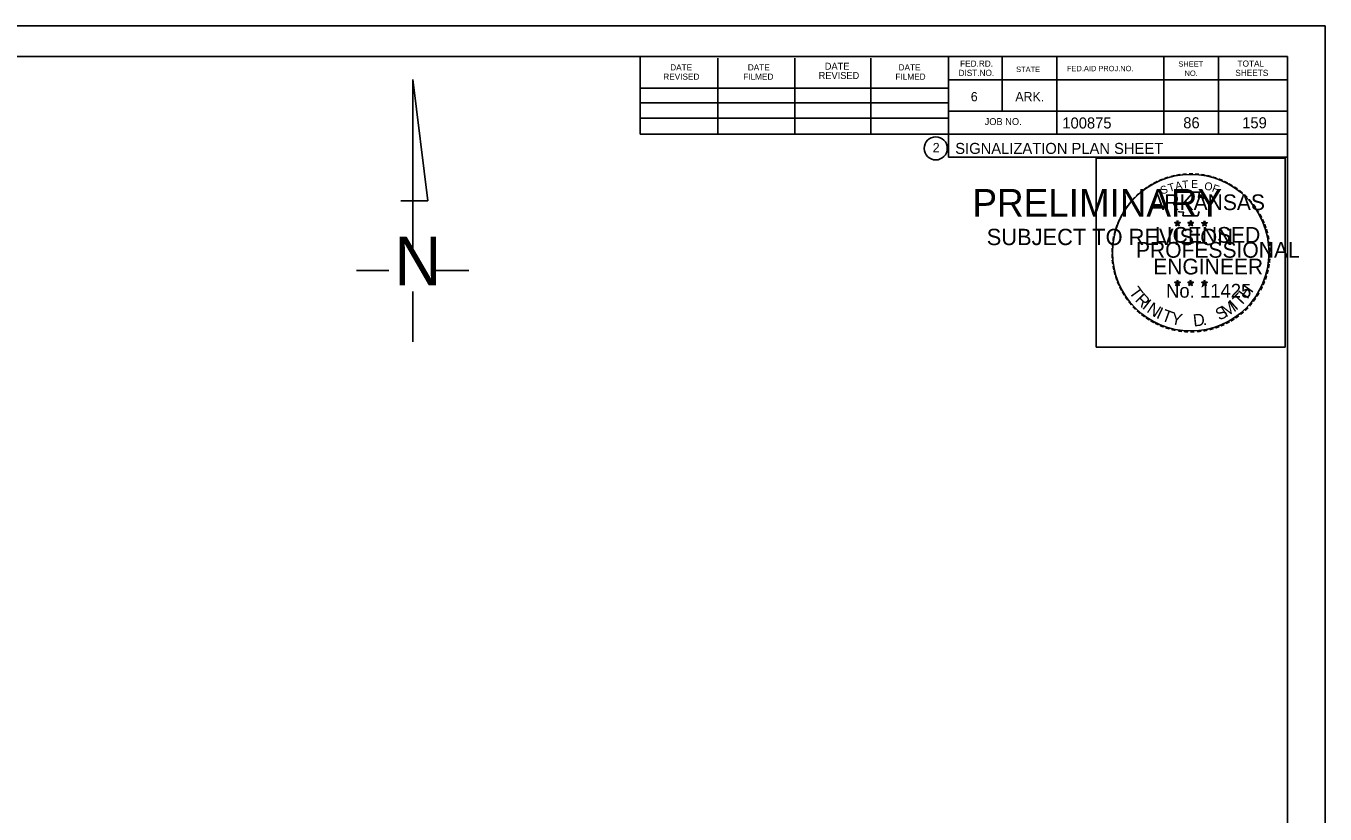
# Model space of a CAD drawing. Extents: x 1712074 to 1713074, y 558397 to 559037.
# Drawn here: x 1712578.9 to 1713074.1, y 558736.4 to 559037 of the extents above; entities that cross this region are included whole.
import ezdxf

# ---------------------------------------------------------------- set-up
doc = ezdxf.new("R2010")
doc.units = 0
for name, color, linetype in [('R_Border', 7, 'Continuous'), ('R_Border PE', 7, 'Continuous'), ('R_Border Prem', 7, 'Continuous'), ('R_Draft', 7, 'Continuous'), ('R_No Plot', 7, 'Continuous')]:
    doc.layers.add(name, color=color, linetype=linetype)

msp = doc.modelspace()

# ---------------------------------------------------------------- linework, layer by layer
at = {"layer": 'R_Border'}
for p, q in [((1712111.35, 559025.27), (1713059.89, 559025.27)), ((1712813.11, 558995.63), (1712813.11, 559025.27)), ((1712842.69, 558995.63), (1712842.69, 559024.67)), ((1712871.97, 558995.63), (1712871.97, 559024.67)), ((1712901.01, 558995.63), (1712901.01, 559024.67)), ((1712930.59, 559025.27), (1712930.59, 558986.87)), ((1712951.11, 559025.27), (1712951.11, 559004.45)), ((1712971.93, 559025.27), (1712971.93, 558995.63)), ((1713012.67, 559025.27), (1713012.67, 558995.63)), ((1713033.49, 559025.27), (1713033.49, 558995.63)), ((1713059.89, 558408.89), (1713059.89, 559025.27)), ((1713059.89, 559016.45), (1712930.59, 559016.45)), ((1713059.89, 559016.51), (1713059.89, 559016.51)), ((1712813.11, 559013.21), (1712930.59, 559013.21)), ((1712813.11, 559007.63), (1712930.59, 559007.63)), ((1713059.89, 559004.45), (1712930.59, 559004.45)), ((1712939.47, 559004.45), (1713059.89, 559004.45)), ((1712813.11, 558995.63), (1712813.11, 559001.81)), ((1712813.11, 559001.81), (1712930.59, 559001.81)), ((1713059.89, 558995.63), (1712813.11, 558995.63)), ((1712930.59, 558986.87), (1713059.89, 558986.87))]:
    msp.add_line(p, q, dxfattribs=at)
msp.add_circle((1712925.75, 558990.27), 4.4, dxfattribs=at)
at = {"layer": 'R_Border PE'}
for p, q in [((1713016.87, 558961.95), (1713017.92, 558961.62)), ((1713016.87, 558961.95), (1713017.63, 558961.81)), ((1713016.87, 558961.95), (1713017.58, 558961.58)), ((1713017.27, 558960.73), (1713017.92, 558961.62)), ((1713017.27, 558960.73), (1713017.65, 558961.46)), ((1713017.27, 558960.73), (1713017.91, 558961.38)), ((1713017.92, 558962.71), (1713017.79, 558961.96)), ((1713018.55, 558960.73), (1713017.91, 558961.37)), ((1713017.92, 558961.62), (1713017.92, 558962.71)), ((1713017.92, 558962.71), (1713018.06, 558961.96)), ((1713018.96, 558961.95), (1713017.92, 558961.62)), ((1713018.55, 558960.73), (1713017.92, 558961.62)), ((1713018.96, 558961.95), (1713018.1, 558961.8)), ((1713018.55, 558960.73), (1713018.14, 558961.6)), ((1713018.96, 558961.95), (1713018.34, 558961.64)), ((1713021.88, 558961.95), (1713022.93, 558961.62)), ((1713021.88, 558961.95), (1713022.64, 558961.81)), ((1713021.88, 558961.95), (1713022.59, 558961.58)), ((1713022.28, 558960.73), (1713022.93, 558961.62)), ((1713022.28, 558960.73), (1713022.66, 558961.46)), ((1713022.28, 558960.73), (1713022.92, 558961.38)), ((1713022.93, 558962.71), (1713022.8, 558961.96)), ((1713023.56, 558960.73), (1713022.92, 558961.37)), ((1713022.93, 558961.62), (1713022.93, 558962.71)), ((1713022.93, 558962.71), (1713023.07, 558961.96)), ((1713023.97, 558961.95), (1713022.93, 558961.62)), ((1713023.56, 558960.73), (1713022.93, 558961.62)), ((1713023.97, 558961.95), (1713023.11, 558961.8)), ((1713023.56, 558960.73), (1713023.15, 558961.6)), ((1713023.97, 558961.95), (1713023.35, 558961.64)), ((1713027.17, 558961.91), (1713028.22, 558961.58)), ((1713027.17, 558961.91), (1713027.93, 558961.78)), ((1713027.17, 558961.91), (1713027.88, 558961.55)), ((1713027.57, 558960.69), (1713028.22, 558961.58)), ((1713027.57, 558960.69), (1713027.95, 558961.42)), ((1713027.57, 558960.69), (1713028.21, 558961.34)), ((1713028.22, 558962.68), (1713028.09, 558961.92)), ((1713028.86, 558960.69), (1713028.21, 558961.33)), ((1713028.22, 558961.58), (1713028.22, 558962.68)), ((1713028.22, 558962.68), (1713028.36, 558961.93)), ((1713029.26, 558961.91), (1713028.22, 558961.58)), ((1713028.86, 558960.69), (1713028.22, 558961.58)), ((1713029.26, 558961.91), (1713028.4, 558961.77)), ((1713028.86, 558960.69), (1713028.45, 558961.56)), ((1713029.26, 558961.91), (1713028.65, 558961.61)), ((1713017.9, 558939.99), (1713017.78, 558939.24)), ((1713017.9, 558938.9), (1713017.9, 558939.99)), ((1713017.9, 558939.99), (1713018.05, 558939.24)), ((1713022.91, 558939.99), (1713022.79, 558939.24)), ((1713022.91, 558938.9), (1713022.91, 558939.99)), ((1713022.91, 558939.99), (1713023.06, 558939.24)), ((1713028.21, 558939.96), (1713028.09, 558939.21)), ((1713028.21, 558938.87), (1713028.21, 558939.96)), ((1713028.21, 558939.96), (1713028.36, 558939.21)), ((1713016.86, 558939.23), (1713017.9, 558938.9)), ((1713016.86, 558939.23), (1713017.62, 558939.1)), ((1713016.86, 558939.23), (1713017.57, 558938.86)), ((1713017.26, 558938.01), (1713017.9, 558938.9)), ((1713017.26, 558938.01), (1713017.63, 558938.74)), ((1713017.26, 558938.01), (1713017.9, 558938.66)), ((1713018.94, 558939.23), (1713017.9, 558938.9)), ((1713018.54, 558938.01), (1713017.9, 558938.9)), ((1713018.54, 558938.01), (1713017.9, 558938.65)), ((1713018.94, 558939.23), (1713018.09, 558939.08)), ((1713018.54, 558938.01), (1713018.13, 558938.88)), ((1713018.94, 558939.23), (1713018.33, 558938.92)), ((1713021.86, 558939.23), (1713022.91, 558938.9)), ((1713021.86, 558939.23), (1713022.62, 558939.1)), ((1713021.86, 558939.23), (1713022.57, 558938.86)), ((1713022.26, 558938.01), (1713022.91, 558938.9)), ((1713022.26, 558938.01), (1713022.64, 558938.74)), ((1713022.26, 558938.01), (1713022.9, 558938.66)), ((1713023.55, 558938.01), (1713022.9, 558938.65)), ((1713023.95, 558939.23), (1713022.91, 558938.9)), ((1713023.55, 558938.01), (1713022.91, 558938.9)), ((1713023.95, 558939.23), (1713023.09, 558939.08)), ((1713023.55, 558938.01), (1713023.14, 558938.88)), ((1713023.95, 558939.23), (1713023.34, 558938.92)), ((1713027.16, 558939.2), (1713028.21, 558938.87)), ((1713027.16, 558939.2), (1713027.92, 558939.07)), ((1713027.16, 558939.2), (1713027.88, 558938.83)), ((1713027.56, 558937.98), (1713028.21, 558938.87)), ((1713027.56, 558937.98), (1713027.94, 558938.71)), ((1713027.56, 558937.98), (1713028.21, 558938.63)), ((1713029.25, 558939.2), (1713028.21, 558938.87)), ((1713028.85, 558937.98), (1713028.21, 558938.87)), ((1713028.85, 558937.98), (1713028.21, 558938.62)), ((1713029.25, 558939.2), (1713028.39, 558939.05)), ((1713028.85, 558937.98), (1713028.44, 558938.85)), ((1713029.25, 558939.2), (1713028.64, 558938.89))]:
    msp.add_line(p, q, dxfattribs=at)
for points in [[(1713016.99, 558973.58), (1713017.8, 558971.1)], [(1713027.52, 558970.82), (1713027.95, 558971.67), (1713025.9, 558971.6), (1713026.34, 558973.58), (1713016.99, 558973.58)], [(1713018.47, 558966.31), (1713018.47, 558966.05), (1713020.16, 558966), (1713019.99, 558964.58), (1713025.6, 558964.58), (1713026.21, 558966.19)], [(1713017.92, 558962.71), (1713018.55, 558960.73), (1713016.87, 558961.95), (1713018.96, 558961.95), (1713017.27, 558960.73), (1713017.92, 558962.71)], [(1713022.93, 558962.71), (1713023.56, 558960.73), (1713021.88, 558961.95), (1713023.97, 558961.95), (1713022.28, 558960.73), (1713022.93, 558962.71)], [(1713028.22, 558962.68), (1713028.86, 558960.69), (1713027.17, 558961.91), (1713029.26, 558961.91), (1713027.57, 558960.69), (1713028.22, 558962.68)], [(1713017.9, 558939.99), (1713018.54, 558938.01), (1713016.86, 558939.23), (1713018.94, 558939.23), (1713017.26, 558938.01), (1713017.9, 558939.99)], [(1713022.91, 558939.99), (1713023.55, 558938.01), (1713021.86, 558939.23), (1713023.95, 558939.23), (1713022.26, 558938.01), (1713022.91, 558939.99)], [(1713028.21, 558939.96), (1713028.85, 558937.98), (1713027.16, 558939.2), (1713029.25, 558939.2), (1713027.56, 558937.98), (1713028.21, 558939.96)]]:
    msp.add_lwpolyline(points, dxfattribs=at)
for centre, radius in [((1713017.91, 558961.61), 0.517), ((1713017.91, 558961.61), 0.434), ((1713017.91, 558961.61), 0.347), ((1713017.91, 558961.61), 0.297), ((1713017.91, 558961.61), 0.224), ((1713017.91, 558961.61), 0.149), ((1713017.91, 558961.61), 0.0889), ((1713022.92, 558961.61), 0.517), ((1713022.92, 558961.61), 0.434), ((1713022.92, 558961.61), 0.347), ((1713022.92, 558961.61), 0.297), ((1713022.92, 558961.61), 0.224), ((1713022.92, 558961.61), 0.149), ((1713022.92, 558961.61), 0.0889), ((1713028.21, 558961.58), 0.517), ((1713028.21, 558961.58), 0.434), ((1713028.21, 558961.58), 0.347), ((1713028.21, 558961.58), 0.297), ((1713028.21, 558961.58), 0.224), ((1713028.21, 558961.58), 0.149), ((1713028.21, 558961.58), 0.0889), ((1713017.9, 558938.9), 0.517), ((1713017.9, 558938.9), 0.434), ((1713017.9, 558938.9), 0.347), ((1713017.9, 558938.9), 0.297), ((1713017.9, 558938.9), 0.224), ((1713017.9, 558938.9), 0.149), ((1713017.9, 558938.9), 0.0889), ((1713022.91, 558938.9), 0.517), ((1713022.91, 558938.9), 0.434), ((1713022.91, 558938.9), 0.347), ((1713022.91, 558938.9), 0.297), ((1713022.91, 558938.9), 0.224), ((1713022.91, 558938.9), 0.149), ((1713022.91, 558938.9), 0.0889), ((1713028.21, 558938.87), 0.517), ((1713028.21, 558938.87), 0.434), ((1713028.21, 558938.87), 0.347), ((1713028.21, 558938.87), 0.297), ((1713028.21, 558938.87), 0.224), ((1713028.21, 558938.87), 0.149), ((1713028.21, 558938.87), 0.0889)]:
    msp.add_circle(centre, radius, dxfattribs=at)
at = {"layer": 'R_Draft'}
for p, q in [((1712726.36, 559016.5), (1712732.14, 558970.29)), ((1712726.36, 558951.42), (1712726.36, 559016.5)), ((1712721.84, 558970.29), (1712732.14, 558970.29)), ((1712704.95, 558943.74), (1712717.3, 558943.74)), ((1712734.57, 558943.74), (1712747.76, 558943.74)), ((1712726.36, 558916.5), (1712726.36, 558935.64))]:
    msp.add_line(p, q, dxfattribs=at)
at = {"layer": 'R_No Plot'}
for p, q in [((1712074.14, 559036.95), (1713074.14, 559036.95)), ((1712986.72, 558917.82), (1712986.72, 558917.82))]:
    msp.add_line(p, q, dxfattribs=at)
for points in [[(1712074.12, 559036.95), (1713074.14, 559036.95), (1713074.14, 558396.94), (1712074.12, 558396.94)], [(1712986.95, 558986.5), (1713058.95, 558986.5), (1713058.95, 558914.5), (1712986.95, 558914.5)]]:
    msp.add_lwpolyline(points, close=True, dxfattribs=at)
msp.add_circle((1713022.95, 558950.5), 29.86, dxfattribs=at)

# ---------------------------------------------------------------- texts
at = {"layer": 'R_Border'}
for s, height, p in [('DATE', 2.346, (1712824.51, 559019.99)), ('DATE', 2.346, (1712854.09, 559019.99)), ('REVISED', 2.638, (1712881.09, 559016.75)), ('DATE', 2.638, (1712883.43, 559020.29)), ('DATE', 2.346, (1712911.57, 559019.99)), ('DIST.NO.', 2.346, (1712934.43, 559017.89)), ('FED.RD.', 2.346, (1712935.03, 559021.43)), ('STATE', 2.052, (1712956.39, 559019.39)), ('FED.AID PROJ.NO.', 2.052, (1712975.77, 559019.69)), ('SHEET', 2.052, (1713018.25, 559021.43)), ('NO.', 2.052, (1713020.59, 559017.89)), ('SHEETS', 2.346, (1713039.97, 559017.89)), ('TOTAL', 2.346, (1713040.81, 559021.43)), ('REVISED', 2.346, (1712821.87, 559016.45)), ('FILMED', 2.346, (1712852.35, 559016.45)), ('FILMED', 2.346, (1712910.37, 559016.45)), ('6', 3.52, (1712939.11, 559008.23)), ('ARK.', 3.517, (1712956.09, 559008.23)), ('JOB NO.', 2.638, (1712944.39, 558999.17)), ('100875', 4.2, (1712974.01, 558997.85)), ('86', 4.2, (1713020.1, 558997.94)), ('159', 4.2, (1713042.58, 558997.94)), ('2', 3.52, (1712924.6, 558988.82)), ('SIGNALIZATION PLAN SHEET', 4.2, (1712933.18, 558988.16))]:
    msp.add_text(s, height=height, dxfattribs=at).set_placement(p)
at = {"layer": 'R_Border PE'}
for s, height, rotation, p in [('-', 4.8, 19.1761, (1713013.23, 558976.96)), ('-', 4.8, 13.6302, (1713015.48, 558977.69)), ('-', 4.8, 10.2193, (1713017.52, 558978.17)), ('-', 4.8, 5.8968, (1713019.71, 558978.5)), ('-', 4.8, 0.1862, (1713022.02, 558978.72)), ('-', 4.8, 357.743, (1713024.19, 558978.68)), ('-', 4.8, 352.1617, (1713026.42, 558978.51)), ('-', 4.8, 347.2049, (1713028.58, 558978.17)), ('-', 4.8, 342.3362, (1713030.48, 558977.71)), ('-', 4.8, 38.9507, (1713004.48, 558971.78)), ('-', 4.8, 36.2317, (1713005.91, 558972.91)), ('-', 4.8, 34.0636, (1713007.64, 558974.1)), ('-', 4.8, 28.7918, (1713009.43, 558975.21)), ('-', 4.8, 24.3072, (1713011.33, 558976.16)), ('S', 3, 21.594, (1713012.06, 558972.62)), ('T', 3, 16.4036, (1713014.8, 558973.61)), ('A', 3, 11.2132, (1713017.28, 558974.36)), ('T', 3, 6.0228, (1713019.82, 558974.86)), ('E', 3, 0.8323, (1713023.14, 558975.19)), ('O', 3, 350.4515, (1713027.95, 558974.56)), ('F', 3, 340.0707, (1713030.81, 558973.88)), ('-', 4.8, 337.8551, (1713032.69, 558977.04)), ('-', 4.8, 334.1211, (1713034.58, 558976.22)), ('-', 4.8, 329.6409, (1713036.32, 558975.37)), ('-', 4.8, 325.8627, (1713038.25, 558974.29)), ('-', 4.8, 320.5297, (1713040.08, 558973.01)), ('-', 4.8, 50.6142, (1713000.63, 558967.63)), ('-', 4.8, 48.4231, (1713001.84, 558969.09)), ('-', 4.8, 42.9622, (1713003.18, 558970.53)), ('-', 4.8, 315.5786, (1713041.88, 558971.55)), ('-', 4.8, 309.8797, (1713043.58, 558969.9)), ('-', 4.8, 62.8713, (1712997.48, 558962.51)), ('-', 4.8, 58.0706, (1712998.41, 558964.35)), ('-', 4.8, 54.2325, (1712999.39, 558965.93)), ('-', 4.8, 306.6522, (1713045.16, 558968.09)), ('-', 4.2, 303.6753, (1713046.62, 558966.39)), ('-', 4.8, 299.6684, (1713047.57, 558964.57)), ('-', 4.8, 72.3945, (1712996.04, 558958.79)), ('-', 4.8, 67.7743, (1712996.7, 558960.68)), ('-', 4.8, 294.6628, (1713048.54, 558962.73)), ('-', 4.8, 290.5728, (1713049.32, 558961)), ('-', 4.8, 285.1233, (1713050.02, 558959.26)), ('-', 4.8, 81.2013, (1712995.05, 558954.51)), ('-', 4.8, 75.461, (1712995.45, 558956.65)), ('-', 4.8, 280.5493, (1713050.62, 558957.04)), ('-', 4.8, 276.5962, (1713051.1, 558954.73)), ('-', 4.8, 94.1959, (1712994.86, 558948.16)), ('-', 4.8, 89.0622, (1712994.75, 558950.33)), ('-', 4.8, 85.1863, (1712994.83, 558952.43)), ('-', 4.8, 274.3301, (1713051.28, 558952.57)), ('-', 4.8, 269.9407, (1713051.39, 558950.67)), ('-', 4.8, 98.9479, (1712995.07, 558946.15)), ('-', 4.8, 101.7149, (1712995.48, 558943.96)), ('-', 4.8, 260.9953, (1713051.12, 558946.71)), ('-', 4.8, 263.5172, (1713051.33, 558948.67)), ('-', 4.8, 105.4578, (1712995.96, 558942.17)), ('-', 4.8, 109.0874, (1712996.61, 558940.28)), ('-', 4.8, 252.8681, (1713050.24, 558942.52)), ('-', 4.8, 255.7626, (1713050.79, 558944.68)), ('-', 4.8, 114.0643, (1712997.37, 558938.49)), ('-', 4.8, 115.7289, (1712998.29, 558936.64)), ('-', 4.8, 120.4471, (1712999.36, 558934.88)), ('T', 4.62, 306.0406, (1712999.18, 558935.41)), ('R', 4.62, 314.005, (1713001.47, 558932.27)), ('T', 4.62, 46.6444, (1713041.87, 558929.69)), ('H', 4.62, 54.6088, (1713044.54, 558932.52)), ('-', 4.8, 239.0712, (1713047.61, 558936.35)), ('-', 4.8, 244.6197, (1713048.79, 558938.61)), ('-', 4.8, 247.8887, (1713049.57, 558940.5)), ('-', 4.8, 125.8934, (1713000.57, 558933.19)), ('-', 4.8, 130.7181, (1713001.95, 558931.54)), ('-', 4.8, 134.2238, (1713003.5, 558929.9)), ('I', 4.62, 321.9694, (1713004.17, 558929.47)), ('N', 4.62, 326.5002, (1713005.87, 558928.06)), ('S', 4.62, 26.9312, (1713033.82, 558924.5)), ('M', 4.62, 32.6563, (1713036.34, 558925.72)), ('I', 4.62, 42.1136, (1713040.19, 558928.26)), ('-', 4.8, 231.2538, (1713045.11, 558932.7)), ('-', 4.8, 233.8452, (1713046.4, 558934.39)), ('-', 4.8, 138.9338, (1713005.08, 558928.51)), ('-', 4.8, 144.6463, (1713006.75, 558927.29)), ('-', 4.8, 148.0898, (1713008.43, 558926.18)), ('I', 4.62, 335.3603, (1713009.5, 558925.7)), ('T', 4.62, 339.8912, (1713011.48, 558924.72)), ('Y', 4.62, 347.8556, (1713015.13, 558923.38)), ('D', 4.62, 6.3969, (1713024.09, 558922.31)), ('-', 4.8, 212.2491, (1713038.86, 558926.9)), ('-', 4.8, 215.7363, (1713040.46, 558928.06)), ('-', 4.8, 221.0851, (1713042.11, 558929.48)), ('-', 4.8, 225.7653, (1713043.67, 558931)), ('-', 4.8, 151.5704, (1713010.17, 558925.21)), ('-', 4.8, 154.6002, (1713011.73, 558924.46)), ('-', 4.8, 158.5612, (1713013.6, 558923.7)), ('-', 4.8, 162.7983, (1713015.66, 558923.06)), ('-', 4.8, 167.5555, (1713017.81, 558922.57)), ('-', 4.8, 173.1155, (1713020.13, 558922.24)), ('-', 4.8, 176.5183, (1713022.37, 558922.08)), ('-', 4.8, 181.5918, (1713024.6, 558922.14)), ('-', 4.8, 185.8167, (1713027.03, 558922.37)), ('-', 4.8, 191.2858, (1713029.24, 558922.76)), ('.', 4.62, 13.7642, (1713027.66, 558922.69)), ('-', 4.8, 195.4743, (1713031.42, 558923.36)), ('-', 4.8, 200.7184, (1713033.45, 558924.09)), ('-', 4.8, 204.2516, (1713035.31, 558924.91)), ('-', 4.8, 207.3568, (1713037.18, 558925.86))]:
    msp.add_text(s, height=height, rotation=rotation, dxfattribs=at).set_placement(p)
for s, height, p in [('ARKANSAS', 6, (1713007.55, 558966.72)), ('LICENSED', 6, (1713009.34, 558954.27)), ('DWB', 0.03, (1713017.88, 558961.6)), ('DWB', 0.03, (1713022.89, 558961.6)), ('DWB', 0.03, (1713028.18, 558961.57)), ('PROFESSIONAL', 6, (1713002.07, 558948.56)), ('ENGINEER', 6, (1713008.63, 558942.19)), ('No. 11425', 5.271, (1713013.52, 558933.33)), ('DWB', 0.03, (1713017.86, 558938.88)), ('DWB', 0.03, (1713022.87, 558938.88)), ('DWB', 0.03, (1713028.17, 558938.85))]:
    msp.add_text(s, height=height, dxfattribs=at).set_placement(p)
at = {"layer": 'R_Border Prem'}
for s, height, p in [('PRELIMINARY', 10.5, (1712939.74, 558964.26)), ('SUBJECT TO REVISION', 6.2253, (1712945.17, 558953.37))]:
    msp.add_text(s, height=height, dxfattribs=at).set_placement(p)
at = {"layer": 'R_Draft'}
msp.add_text('N', height=18.61, dxfattribs=at).set_placement((1712719.3, 558938.01))

doc.saveas('drawing.dxf')
